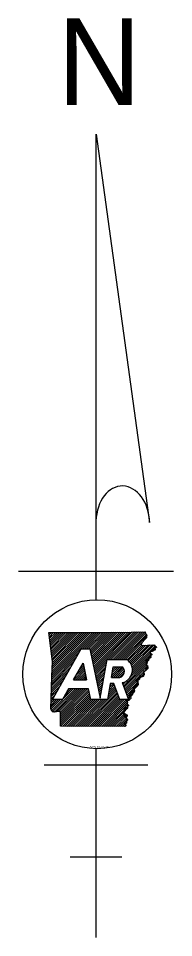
# Model space of a CAD drawing. Extents: x 19118 to 454486, y 1325406 to 1693506.
# Drawn here: x 24886.3 to 24956.5, y 1326557.4 to 1326972.5 of the extents above; entities that cross this region are included whole.
import ezdxf

# ---------------------------------------------------------------- set-up
doc = ezdxf.new("R2010")
doc.units = 0
doc.layers.add('S_CURB', color=7, linetype='Continuous')
doc.layers.add('S_MSC_PT_SYM', color=7, linetype='Continuous')

msp = doc.modelspace()

# ---------------------------------------------------------------- linework, layer by layer
at = {"layer": 'S_CURB'}
for p, q in [((24921.39, 1326920.15), (24945.64, 1326744.85)), ((24921.39, 1326709.94), (24921.39, 1326920.15)), ((24886.28, 1326722.94), (24956.48, 1326722.94)), ((24901.74, 1326664.86), (24914.7, 1326687.75)), ((24914.7, 1326687.75), (24918.55, 1326687.75)), ((24911.27, 1326673.84), (24915.51, 1326681.33)), ((24926.37, 1326682.97), (24935.37, 1326682.97)), ((24929.17, 1326679.74), (24933.4, 1326679.74)), ((24911.27, 1326673.84), (24917.11, 1326673.84)), ((24929.41, 1326672.14), (24927.85, 1326672.14)), ((24928.32, 1326674.85), (24932.18, 1326674.85)), ((24932.1, 1326664.86), (24929.41, 1326672.14)), ((24933.22, 1326672.53), (24936.05, 1326664.86)), ((24908.9, 1326669.66), (24906.18, 1326664.86)), ((24918.01, 1326669.66), (24908.9, 1326669.66)), ((24906.18, 1326664.86), (24901.74, 1326664.86)), ((24926.58, 1326664.86), (24919.04, 1326664.86)), ((24936.05, 1326664.86), (24932.1, 1326664.86)), ((24921.39, 1326557.38), (24921.39, 1326642.7)), ((24897.99, 1326635.45), (24944.79, 1326635.45)), ((24909.68, 1326593.88), (24933.09, 1326593.88))]:
    msp.add_line(p, q, dxfattribs=at)
for points in [[(24900.05, 1326695.16), (24912.87, 1326695.16), (24924.13, 1326695.19), (24937.39, 1326695.39), (24943.55, 1326695.54)], [(24900.05, 1326695.17), (24912.87, 1326695.16), (24924.12, 1326695.19), (24937.39, 1326695.39), (24943.55, 1326695.54)], [(24900.98, 1326660.49), (24901.7, 1326682), (24900.05, 1326695.17)], [(24901.47, 1326675.24), (24901.69, 1326682), (24900.05, 1326695.16)], [(24947.57, 1326689.65), (24948.68, 1326688.49), (24945.92, 1326686.21), (24946.21, 1326683.92), (24943.84, 1326682.36), (24944.66, 1326678.83), (24942.83, 1326677.16), (24942.66, 1326675.34), (24940.44, 1326674.54), (24940.09, 1326671.12), (24938.5, 1326669.41), (24937.72, 1326666.84), (24935.4, 1326664.71), (24935.57, 1326660.95), (24933.99, 1326659.18), (24935.43, 1326655.95), (24934.44, 1326652.75)], [(24941.64, 1326689.35), (24947.66, 1326689.65)], [(24941.64, 1326689.34), (24947.66, 1326689.65)], [(24918.55, 1326687.75), (24923.32, 1326665.47), (24926.37, 1326682.97)], [(24915.51, 1326681.33), (24917.11, 1326673.84)], [(24928.32, 1326674.85), (24929.17, 1326679.74)], [(24900.98, 1326660.49), (24901.47, 1326675.24)], [(24927.85, 1326672.14), (24926.58, 1326664.86)], [(24919.04, 1326664.86), (24918.01, 1326669.66)], [(24934.43, 1326652.75), (24905.38, 1326652.8), (24905.37, 1326659.21)], [(24934.44, 1326652.75), (24905.38, 1326652.8), (24905.37, 1326659.21)]]:
    msp.add_lwpolyline(points, dxfattribs=at)
for centre, major_axis, ratio, start_param, end_param in [((24933.51, 1326744.48), (-0.52, 16.85), 0.719778, 4.712385, 7.768526), ((24932.02, 1326678.22), (-5.82, 0), 0.999987, 1.777838, 4.099264), ((24931.26, 1326677.68), (-2.97, 0), 0.999987, 1.887169, 3.90762)]:
    msp.add_ellipse(centre, major_axis=major_axis, ratio=ratio, start_param=start_param, end_param=end_param, dxfattribs=at)
msp.add_ellipse((24921.93, 1326676.32), major_axis=(33.63, 0), ratio=0.999976, dxfattribs=at)
for points in [[(24943.55, 1326695.54), (24943.59, 1326695.19), (24943.69, 1326695.01), (24943.71, 1326694.67), (24943.85, 1326694.53), (24944.08, 1326694.39), (24944.28, 1326694.16), (24944.33, 1326693.89), (24944.26, 1326693.61), (24944.25, 1326693.3), (24944.22, 1326693.03), (24944.17, 1326692.79), (24943.98, 1326692.59), (24943.8, 1326692.45), (24943.63, 1326692.28), (24943.51, 1326692.1), (24943.31, 1326691.92), (24943.1, 1326691.71), (24942.93, 1326691.54), (24942.77, 1326691.32), (24942.69, 1326691.08), (24942.51, 1326690.9), (24942.36, 1326690.74), (24942.17, 1326690.52), (24942.08, 1326690.31), (24941.9, 1326690.07), (24941.86, 1326689.83), (24941.74, 1326689.64), (24941.73, 1326689.61)], [(24943.55, 1326695.54), (24943.59, 1326695.19), (24943.7, 1326695.01), (24943.71, 1326694.67), (24943.85, 1326694.53), (24944.08, 1326694.39), (24944.28, 1326694.16), (24944.33, 1326693.89), (24944.27, 1326693.61), (24944.25, 1326693.3), (24944.22, 1326693.03), (24944.17, 1326692.79), (24943.98, 1326692.59), (24943.8, 1326692.44), (24943.63, 1326692.28), (24943.51, 1326692.1), (24943.31, 1326691.91), (24943.1, 1326691.72), (24942.94, 1326691.54), (24942.77, 1326691.32), (24942.69, 1326691.07), (24942.51, 1326690.9), (24942.36, 1326690.74), (24942.17, 1326690.53), (24942.08, 1326690.31), (24941.9, 1326690.07), (24941.86, 1326689.83), (24941.74, 1326689.64), (24941.73, 1326689.61)], [(24947.57, 1326689.65), (24947.66, 1326689.65), (24947.93, 1326689.37), (24948.05, 1326689.13), (24948.22, 1326689), (24948.42, 1326688.93), (24948.57, 1326688.74), (24948.67, 1326688.54), (24948.62, 1326688.37), (24948.39, 1326688.35), (24948.15, 1326688.31), (24947.91, 1326688.32), (24947.72, 1326688.16), (24947.9, 1326687.95), (24948.13, 1326687.75), (24948.19, 1326687.54), (24948.06, 1326687.33), (24947.81, 1326687.22), (24947.56, 1326687.12), (24947.34, 1326686.94), (24947.24, 1326686.75), (24946.99, 1326686.67), (24946.74, 1326686.6), (24946.52, 1326686.58), (24946.27, 1326686.53), (24946.02, 1326686.41), (24945.92, 1326686.21), (24945.95, 1326685.91), (24945.94, 1326685.6), (24946.2, 1326685.5), (24946.43, 1326685.49), (24946.66, 1326685.38), (24946.63, 1326685.2), (24946.46, 1326684.98), (24946.27, 1326684.8), (24946.07, 1326684.72), (24945.88, 1326684.55), (24945.95, 1326684.38), (24946.11, 1326684.27), (24946.23, 1326684.09), (24946.22, 1326683.92), (24946.03, 1326683.8), (24945.82, 1326683.85), (24945.67, 1326684.05), (24945.5, 1326684.11), (24945.34, 1326684.18), (24945.17, 1326684.08), (24945.17, 1326683.85), (24945.11, 1326683.61), (24945.16, 1326683.43), (24945.23, 1326683.17), (24945.22, 1326682.98), (24945.16, 1326682.71), (24945.02, 1326682.43), (24944.87, 1326682.35), (24944.8, 1326682.65), (24944.77, 1326682.89), (24944.68, 1326683.04), (24944.55, 1326683.04), (24944.38, 1326682.93), (24944.2, 1326682.74), (24943.98, 1326682.54), (24943.84, 1326682.35), (24943.91, 1326682.1), (24944.08, 1326682.04), (24944.22, 1326682.08), (24944.29, 1326682.24), (24944.42, 1326682.26), (24944.55, 1326682.02)], [(24944.55, 1326682.02), (24944.59, 1326681.79), (24944.45, 1326681.55), (24944.4, 1326681.3), (24944.42, 1326681.05), (24944.17, 1326680.92), (24943.95, 1326680.76), (24944.08, 1326680.57), (24944.32, 1326680.39), (24944.55, 1326680.26), (24944.7, 1326680.12), (24944.74, 1326679.8), (24944.78, 1326679.59), (24944.86, 1326679.31), (24944.89, 1326679.11), (24944.75, 1326678.87), (24944.59, 1326678.82), (24944.41, 1326678.88), (24944.2, 1326678.89), (24944.04, 1326678.74), (24943.92, 1326678.52), (24943.8, 1326678.29), (24943.71, 1326678.1), (24943.62, 1326677.9), (24943.45, 1326677.66), (24943.24, 1326677.62), (24942.98, 1326677.56), (24942.83, 1326677.38), (24942.86, 1326677.09), (24943, 1326676.89), (24943.11, 1326676.65), (24943.19, 1326676.43), (24943.15, 1326676.16), (24943.04, 1326675.96), (24942.9, 1326675.84), (24942.83, 1326675.59), (24942.73, 1326675.4), (24942.63, 1326675.33), (24942.44, 1326675.35), (24942.24, 1326675.39), (24942.06, 1326675.38), (24941.9, 1326675.29), (24941.73, 1326675.34), (24941.56, 1326675.54), (24941.41, 1326675.68), (24941.25, 1326675.73), (24941.09, 1326675.65), (24941.06, 1326675.38), (24941.14, 1326675.11), (24941.21, 1326674.75), (24941.14, 1326674.53), (24941.11, 1326674.16)], [(24941.11, 1326674.16), (24940.84, 1326673.95), (24940.71, 1326673.73), (24940, 1326673.8), (24940.02, 1326673.55), (24939.77, 1326673.42), (24939.55, 1326673.26), (24939.68, 1326673.07), (24939.92, 1326672.89), (24940.15, 1326672.76), (24940.3, 1326672.63), (24940.34, 1326672.29), (24940.38, 1326672.09), (24940.46, 1326671.8), (24940.49, 1326671.61), (24940.35, 1326671.37), (24940.18, 1326671.32), (24940.01, 1326671.38), (24939.81, 1326671.39), (24939.64, 1326671.24), (24939.52, 1326671.01), (24939.4, 1326670.79), (24939.31, 1326670.6), (24939.22, 1326670.39), (24939.05, 1326670.15), (24938.84, 1326670.12), (24938.59, 1326670.05), (24938.43, 1326669.88), (24938.46, 1326669.59), (24938.6, 1326669.39), (24938.71, 1326669.14), (24938.79, 1326668.93), (24938.76, 1326668.66), (24938.64, 1326668.46), (24938.5, 1326668.34), (24938.43, 1326668.09), (24938.33, 1326667.89), (24938.24, 1326667.84), (24938.05, 1326667.85), (24937.84, 1326667.89), (24937.67, 1326667.88), (24937.5, 1326667.79), (24937.33, 1326667.84), (24937.16, 1326668.03), (24937.01, 1326668.18), (24936.86, 1326668.23), (24936.69, 1326668.15), (24936.66, 1326667.88), (24936.74, 1326667.62), (24936.81, 1326667.25), (24936.74, 1326667.03), (24936.72, 1326666.66)], [(24935.65, 1326663.68), (24935.57, 1326663.49), (24935.48, 1326663.18), (24935.51, 1326662.91), (24935.63, 1326662.68), (24935.81, 1326662.55), (24936.03, 1326662.37), (24936.01, 1326662.09), (24935.89, 1326661.99), (24935.6, 1326662.06), (24935.39, 1326662.16), (24935.21, 1326662.1), (24934.97, 1326661.98), (24934.79, 1326661.95), (24934.79, 1326661.57), (24935.04, 1326661.3), (24935.25, 1326661.3), (24935.5, 1326661.27), (24935.59, 1326660.99), (24935.44, 1326660.75), (24935.21, 1326660.63), (24934.9, 1326660.78), (24934.69, 1326660.93), (24934.48, 1326661.07), (24934.21, 1326661.14), (24934.05, 1326661.11), (24933.98, 1326660.78), (24934.11, 1326660.47), (24934.31, 1326660.26), (24934.51, 1326660), (24934.48, 1326659.8), (24934.33, 1326659.74), (24934.08, 1326659.69), (24933.93, 1326659.61), (24933.89, 1326659.55), (24933.97, 1326659.28), (24934.04, 1326658.99), (24934.04, 1326658.76), (24933.95, 1326658.56), (24933.82, 1326658.24), (24933.83, 1326658.04), (24933.93, 1326657.94), (24934.05, 1326657.97), (24934.21, 1326658.08), (24934.31, 1326658.21), (24934.4, 1326658.37), (24934.56, 1326658.5), (24934.77, 1326658.38), (24934.82, 1326658.13), (24934.7, 1326657.92), (24934.53, 1326657.82), (24934.33, 1326657.74), (24934.18, 1326657.57), (24934.21, 1326657.36), (24934.33, 1326657.25), (24934.63, 1326657.31), (24934.82, 1326657.4), (24934.94, 1326657.5), (24935.07, 1326657.64), (24935.14, 1326657.78), (24935.25, 1326657.92), (24935.43, 1326657.96), (24935.52, 1326657.84), (24935.48, 1326657.57), (24935.37, 1326657.32), (24935.22, 1326657.1), (24935.05, 1326656.96), (24934.85, 1326656.63), (24934.89, 1326656.33), (24934.97, 1326656.08), (24935.07, 1326655.89), (24935.27, 1326655.93), (24935.48, 1326655.95), (24935.6, 1326655.85), (24935.59, 1326655.63), (24935.44, 1326655.41), (24935.28, 1326655.21), (24935.21, 1326654.93), (24935.24, 1326654.72), (24935.24, 1326654.55), (24935.17, 1326654.34), (24935.06, 1326654.23), (24934.77, 1326654.24), (24934.46, 1326654.27), (24934.3, 1326654.18), (24934.33, 1326653.91), (24934.51, 1326653.71), (24934.63, 1326653.61), (24934.82, 1326653.39), (24934.89, 1326653.2), (24934.87, 1326653.04), (24934.76, 1326652.9), (24934.43, 1326652.75)], [(24935.65, 1326663.68), (24935.57, 1326663.49), (24935.48, 1326663.18), (24935.51, 1326662.91), (24935.63, 1326662.68), (24935.81, 1326662.55), (24936.03, 1326662.37), (24936.01, 1326662.09), (24935.89, 1326661.99), (24935.6, 1326662.06), (24935.39, 1326662.16), (24935.21, 1326662.1), (24934.97, 1326661.98), (24934.79, 1326661.95), (24934.79, 1326661.57), (24935.04, 1326661.3), (24935.25, 1326661.3), (24935.5, 1326661.27), (24935.59, 1326660.99), (24935.44, 1326660.75), (24935.21, 1326660.63), (24934.9, 1326660.78), (24934.69, 1326660.93), (24934.48, 1326661.07), (24934.21, 1326661.14), (24934.05, 1326661.11), (24933.98, 1326660.78), (24934.11, 1326660.47), (24934.31, 1326660.26), (24934.51, 1326660), (24934.48, 1326659.8), (24934.33, 1326659.74), (24934.08, 1326659.69), (24933.93, 1326659.61), (24933.89, 1326659.55), (24933.97, 1326659.28), (24934.04, 1326658.99), (24934.04, 1326658.76), (24933.95, 1326658.56), (24933.82, 1326658.24), (24933.83, 1326658.04), (24933.93, 1326657.94), (24934.05, 1326657.97), (24934.21, 1326658.08), (24934.31, 1326658.21), (24934.4, 1326658.37), (24934.56, 1326658.5), (24934.77, 1326658.38), (24934.82, 1326658.13), (24934.7, 1326657.92), (24934.53, 1326657.82), (24934.33, 1326657.74), (24934.18, 1326657.57), (24934.21, 1326657.36), (24934.33, 1326657.25), (24934.63, 1326657.31), (24934.82, 1326657.4), (24934.94, 1326657.5), (24935.07, 1326657.64), (24935.14, 1326657.78), (24935.25, 1326657.92), (24935.43, 1326657.96), (24935.52, 1326657.84), (24935.48, 1326657.57), (24935.37, 1326657.32), (24935.22, 1326657.1), (24935.05, 1326656.96), (24934.85, 1326656.63), (24934.89, 1326656.33), (24934.97, 1326656.08), (24935.07, 1326655.89), (24935.27, 1326655.93), (24935.48, 1326655.95), (24935.6, 1326655.85), (24935.59, 1326655.63), (24935.44, 1326655.41), (24935.28, 1326655.21), (24935.21, 1326654.93), (24935.24, 1326654.72), (24935.24, 1326654.55), (24935.17, 1326654.34), (24935.06, 1326654.23), (24934.77, 1326654.24), (24934.46, 1326654.27), (24934.3, 1326654.18), (24934.33, 1326653.91), (24934.51, 1326653.71), (24934.63, 1326653.61), (24934.82, 1326653.39), (24934.89, 1326653.2), (24934.87, 1326653.04), (24934.76, 1326652.9), (24934.43, 1326652.75)], [(24936.72, 1326666.66), (24936.7, 1326666.65), (24936.55, 1326666.47), (24936.63, 1326666.19), (24936.94, 1326666.08), (24937.08, 1326665.81), (24937.09, 1326665.57), (24936.99, 1326665.25), (24936.85, 1326665.09), (24936.57, 1326665.03), (24936.36, 1326664.99), (24936.33, 1326664.63), (24936.23, 1326664.45), (24936.06, 1326664.39), (24935.82, 1326664.51), (24935.68, 1326664.57), (24935.51, 1326664.65), (24935.28, 1326664.77), (24935.11, 1326664.75), (24935.16, 1326664.41), (24935.18, 1326664.39), (24935.37, 1326664.13), (24935.56, 1326663.92), (24935.65, 1326663.68)], [(24936.72, 1326666.66), (24936.7, 1326666.65), (24936.55, 1326666.47), (24936.63, 1326666.19), (24936.94, 1326666.08), (24937.08, 1326665.81), (24937.09, 1326665.57), (24936.99, 1326665.25), (24936.85, 1326665.09), (24936.57, 1326665.03), (24936.36, 1326664.99), (24936.33, 1326664.63), (24936.23, 1326664.45), (24936.06, 1326664.39), (24935.82, 1326664.51), (24935.68, 1326664.57), (24935.51, 1326664.65), (24935.28, 1326664.77), (24935.11, 1326664.75), (24935.16, 1326664.41), (24935.18, 1326664.39), (24935.37, 1326664.13), (24935.56, 1326663.92), (24935.65, 1326663.68)], [(24905.37, 1326659.21), (24905.4, 1326659.2), (24905.25, 1326659.3), (24905.04, 1326659.4), (24904.81, 1326659.42), (24904.51, 1326659.46), (24904.27, 1326659.48), (24904.02, 1326659.65), (24903.75, 1326659.48), (24903.45, 1326659.35), (24903.27, 1326659.49), (24903.05, 1326659.39), (24902.88, 1326659.45), (24902.61, 1326659.25), (24902.34, 1326659.32), (24902.16, 1326659.27), (24901.92, 1326659.28), (24901.87, 1326659.55), (24901.64, 1326659.58), (24901.44, 1326659.7), (24901.31, 1326659.97), (24901.21, 1326660.19), (24900.98, 1326660.49)], [(24905.37, 1326659.21), (24905.4, 1326659.2), (24905.25, 1326659.3), (24905.04, 1326659.4), (24904.81, 1326659.42), (24904.52, 1326659.46), (24904.27, 1326659.48), (24904.02, 1326659.65), (24903.75, 1326659.47), (24903.45, 1326659.35), (24903.27, 1326659.49), (24903.04, 1326659.39), (24902.88, 1326659.44), (24902.61, 1326659.25), (24902.35, 1326659.32), (24902.16, 1326659.27), (24901.92, 1326659.28), (24901.87, 1326659.55), (24901.64, 1326659.58), (24901.44, 1326659.7), (24901.31, 1326659.97), (24901.21, 1326660.19), (24900.98, 1326660.49)]]:
    msp.add_spline(points, degree=3, dxfattribs=at)
at = {"layer": 'S_MSC_PT_SYM'}
for p, q in [((24900.09, 1326694.88), (24900.38, 1326695.17)), ((24900.19, 1326694.06), (24901.31, 1326695.17)), ((24900.3, 1326693.23), (24902.24, 1326695.17)), ((24900.4, 1326692.4), (24903.17, 1326695.17)), ((24900.5, 1326691.58), (24904.09, 1326695.17)), ((24900.61, 1326690.75), (24905.02, 1326695.17)), ((24900.71, 1326689.92), (24905.95, 1326695.17)), ((24900.81, 1326689.1), (24906.88, 1326695.17)), ((24900.91, 1326688.27), (24907.81, 1326695.17)), ((24901.02, 1326687.45), (24908.74, 1326695.17)), ((24901.12, 1326686.62), (24909.67, 1326695.17)), ((24901.22, 1326685.79), (24910.6, 1326695.17)), ((24901.33, 1326684.97), (24911.52, 1326695.16)), ((24901.43, 1326684.14), (24912.45, 1326695.16)), ((24901.46, 1326674.88), (24921.76, 1326695.18)), ((24901.49, 1326675.84), (24920.83, 1326695.18)), ((24901.52, 1326676.8), (24919.9, 1326695.18)), ((24901.53, 1326683.31), (24913.38, 1326695.16)), ((24901.56, 1326677.76), (24918.97, 1326695.18)), ((24901.59, 1326678.72), (24918.04, 1326695.17)), ((24901.62, 1326679.68), (24917.11, 1326695.17)), ((24901.63, 1326682.49), (24914.31, 1326695.17)), ((24901.65, 1326680.65), (24916.18, 1326695.17)), ((24901.68, 1326681.61), (24915.24, 1326695.17)), ((24915.26, 1326687.75), (24922.69, 1326695.18)), ((24916.19, 1326687.75), (24923.62, 1326695.19)), ((24917.12, 1326687.75), (24924.56, 1326695.19)), ((24918.05, 1326687.75), (24925.51, 1326695.21)), ((24918.62, 1326687.4), (24926.45, 1326695.22)), ((24918.79, 1326686.63), (24927.39, 1326695.24)), ((24918.95, 1326685.87), (24928.34, 1326695.25)), ((24919.12, 1326685.1), (24929.28, 1326695.27)), ((24919.28, 1326684.34), (24930.22, 1326695.28)), ((24919.44, 1326683.57), (24931.17, 1326695.3)), ((24919.61, 1326682.81), (24932.11, 1326695.31)), ((24919.77, 1326682.04), (24933.06, 1326695.33)), ((24919.93, 1326681.28), (24934, 1326695.34)), ((24920.1, 1326680.51), (24934.94, 1326695.36)), ((24920.26, 1326679.74), (24935.89, 1326695.37)), ((24920.43, 1326678.98), (24936.83, 1326695.38)), ((24920.59, 1326678.21), (24937.78, 1326695.4)), ((24920.75, 1326677.45), (24938.73, 1326695.42)), ((24927.21, 1326682.97), (24939.68, 1326695.45)), ((24928.14, 1326682.97), (24940.63, 1326695.47)), ((24929.07, 1326682.97), (24941.58, 1326695.49)), ((24930, 1326682.97), (24942.53, 1326695.51)), ((24930.92, 1326682.97), (24943.49, 1326695.53)), ((24931.85, 1326682.97), (24943.69, 1326694.81)), ((24932.78, 1326682.97), (24944.14, 1326694.33)), ((24933.71, 1326682.97), (24944.26, 1326693.52)), ((24934.64, 1326682.97), (24942.14, 1326690.47)), ((24935.49, 1326682.89), (24941.96, 1326689.36)), ((24935.99, 1326682.47), (24942.94, 1326689.41)), ((24936.45, 1326681.99), (24943.92, 1326689.46)), ((24936.85, 1326681.46), (24944.9, 1326689.51)), ((24937.19, 1326680.88), (24945.88, 1326689.56)), ((24937.48, 1326680.23), (24946.86, 1326689.61)), ((24937.69, 1326679.52), (24947.74, 1326689.57)), ((24937.82, 1326678.72), (24948.17, 1326689.07)), ((24947.76, 1326687.73), (24948.61, 1326688.58)), ((24901.4, 1326672.96), (24912.75, 1326684.31)), ((24901.43, 1326673.92), (24913.97, 1326686.46)), ((24937.63, 1326676.67), (24946.06, 1326685.1)), ((24937.82, 1326677.79), (24945.95, 1326685.92)), ((24945.02, 1326683.13), (24946.17, 1326684.28)), ((24901.33, 1326671.04), (24910.33, 1326680.03)), ((24901.36, 1326672), (24911.54, 1326682.17)), ((24913.64, 1326678.02), (24915.76, 1326680.15)), ((24914.85, 1326680.17), (24915.6, 1326680.91)), ((24920.92, 1326676.68), (24926.19, 1326681.96)), ((24921.08, 1326675.92), (24925.99, 1326680.83)), ((24933.79, 1326670.97), (24944.09, 1326681.27)), ((24934.04, 1326670.3), (24944.27, 1326680.52)), ((24936.82, 1326674.93), (24943.92, 1326682.03)), ((24901.3, 1326670.07), (24909.11, 1326677.89)), ((24911.32, 1326673.84), (24916.09, 1326678.62)), ((24912.24, 1326673.84), (24916.25, 1326677.85)), ((24912.42, 1326675.88), (24915.93, 1326679.38)), ((24913.17, 1326673.84), (24916.42, 1326677.09)), ((24914.1, 1326673.84), (24916.58, 1326676.32)), ((24921.24, 1326675.15), (24925.8, 1326679.7)), ((24921.41, 1326674.39), (24925.6, 1326678.58)), ((24921.57, 1326673.62), (24925.41, 1326677.45)), ((24921.74, 1326672.86), (24925.21, 1326676.33)), ((24928.33, 1326674.85), (24933.21, 1326679.74)), ((24928.52, 1326675.97), (24932.29, 1326679.74)), ((24928.71, 1326677.1), (24931.36, 1326679.74)), ((24928.91, 1326678.22), (24930.43, 1326679.74)), ((24929.1, 1326679.35), (24929.5, 1326679.74)), ((24929.26, 1326674.85), (24933.73, 1326679.33)), ((24930.18, 1326674.85), (24934.04, 1326678.71)), ((24931.11, 1326674.85), (24934.22, 1326677.96)), ((24932.04, 1326674.85), (24934.14, 1326676.95)), ((24934.29, 1326669.62), (24944.44, 1326679.76)), ((24934.54, 1326668.94), (24944.61, 1326679.01)), ((24941.44, 1326674.9), (24942.74, 1326676.21)), ((24901.24, 1326668.15), (24906.69, 1326673.6)), ((24901.27, 1326669.11), (24907.9, 1326675.75)), ((24915.03, 1326673.84), (24916.75, 1326675.56)), ((24915.96, 1326673.84), (24916.91, 1326674.79)), ((24916.89, 1326673.84), (24917.07, 1326674.03)), ((24921.9, 1326672.09), (24925.01, 1326675.2)), ((24922.06, 1326671.33), (24924.82, 1326674.08)), ((24922.23, 1326670.56), (24924.62, 1326672.95)), ((24922.39, 1326669.79), (24924.42, 1326671.83)), ((24927.52, 1326670.28), (24929.38, 1326672.14)), ((24927.72, 1326671.41), (24928.45, 1326672.14)), ((24933.29, 1326672.33), (24933.57, 1326672.61)), ((24933.54, 1326671.65), (24935.31, 1326673.42)), ((24934.79, 1326668.26), (24940.37, 1326673.83)), ((24935.04, 1326667.58), (24940.26, 1326672.8)), ((24935.3, 1326666.9), (24940.16, 1326671.77)), ((24901.17, 1326666.23), (24904.26, 1326669.32)), ((24901.2, 1326667.19), (24905.47, 1326671.46)), ((24901.34, 1326659.9), (24911.11, 1326669.66)), ((24901.89, 1326659.52), (24912.04, 1326669.66)), ((24902.56, 1326659.26), (24912.97, 1326669.66)), ((24903.67, 1326659.43), (24913.9, 1326669.66)), ((24904.61, 1326659.45), (24914.82, 1326669.66)), ((24905.34, 1326659.24), (24915.75, 1326669.66)), ((24905.37, 1326657.42), (24917.61, 1326669.66)), ((24905.37, 1326658.35), (24916.68, 1326669.66)), ((24905.37, 1326656.49), (24918.1, 1326669.22)), ((24905.38, 1326655.57), (24918.27, 1326668.46)), ((24905.38, 1326654.64), (24918.43, 1326667.69)), ((24907.24, 1326666.72), (24910.18, 1326669.66)), ((24908.45, 1326668.86), (24909.25, 1326669.66)), ((24914.67, 1326652.78), (24930.65, 1326668.77)), ((24915.6, 1326652.78), (24930.9, 1326668.09)), ((24922.56, 1326669.03), (24924.23, 1326670.7)), ((24922.72, 1326668.26), (24924.03, 1326669.58)), ((24922.88, 1326667.5), (24923.84, 1326668.45)), ((24926.74, 1326665.78), (24930.4, 1326669.44)), ((24926.94, 1326666.91), (24930.15, 1326670.12)), ((24927.13, 1326668.03), (24929.9, 1326670.8)), ((24927.33, 1326669.16), (24929.65, 1326671.48)), ((24935.55, 1326666.22), (24938.4, 1326669.07)), ((24935.8, 1326665.55), (24938, 1326667.75)), ((24901, 1326660.48), (24905.38, 1326664.86)), ((24901.01, 1326661.43), (24904.45, 1326664.86)), ((24901.05, 1326662.39), (24903.52, 1326664.86)), ((24901.08, 1326663.35), (24902.59, 1326664.86)), ((24901.11, 1326664.31), (24901.84, 1326665.04)), ((24901.14, 1326665.27), (24903.05, 1326667.18)), ((24905.38, 1326653.71), (24918.59, 1326666.93)), ((24905.4, 1326652.8), (24918.76, 1326666.16)), ((24906.32, 1326652.8), (24918.92, 1326665.39)), ((24907.25, 1326652.8), (24919.31, 1326664.86)), ((24908.18, 1326652.79), (24920.24, 1326664.86)), ((24909.11, 1326652.79), (24921.17, 1326664.86)), ((24910.03, 1326652.79), (24922.1, 1326664.86)), ((24910.96, 1326652.79), (24923.03, 1326664.86)), ((24911.89, 1326652.79), (24923.96, 1326664.86)), ((24912.82, 1326652.79), (24924.89, 1326664.86)), ((24913.74, 1326652.79), (24925.82, 1326664.86)), ((24916.53, 1326652.78), (24931.15, 1326667.41)), ((24917.46, 1326652.78), (24931.41, 1326666.73)), ((24918.38, 1326652.78), (24931.66, 1326666.05)), ((24919.31, 1326652.78), (24931.91, 1326665.37)), ((24920.24, 1326652.77), (24932.32, 1326664.86)), ((24921.17, 1326652.77), (24933.25, 1326664.86)), ((24922.09, 1326652.77), (24934.18, 1326664.86)), ((24923.02, 1326652.77), (24935.11, 1326664.86)), ((24923.05, 1326666.73), (24923.64, 1326667.33)), ((24923.21, 1326665.97), (24923.44, 1326666.2)), ((24923.95, 1326652.77), (24935.42, 1326664.24)), ((24924.88, 1326652.77), (24935.46, 1326663.35)), ((24925.8, 1326652.77), (24935.5, 1326662.47)), ((24926.73, 1326652.76), (24935.55, 1326661.58)), ((24927.66, 1326652.76), (24934.02, 1326659.12)), ((24928.59, 1326652.76), (24934.31, 1326658.48)), ((24929.51, 1326652.76), (24934.59, 1326657.84)), ((24930.44, 1326652.76), (24934.88, 1326657.2)), ((24931.37, 1326652.76), (24935.17, 1326656.55)), ((24932.3, 1326652.75), (24935.41, 1326655.86)), ((24933.23, 1326652.75), (24934.99, 1326654.51)), ((24934.15, 1326652.75), (24934.57, 1326653.16))]:
    msp.add_line(p, q, dxfattribs=at)

# ---------------------------------------------------------------- texts
at = {"layer": 'S_CURB'}
for s, height, p in [('N', 39.12, (24903.95, 1326933.38)), ('STS 10-03-17', 0.9722, (24918.72, 1326642.97))]:
    msp.add_text(s, height=height, dxfattribs=at).set_placement(p)

doc.saveas('drawing.dxf')
